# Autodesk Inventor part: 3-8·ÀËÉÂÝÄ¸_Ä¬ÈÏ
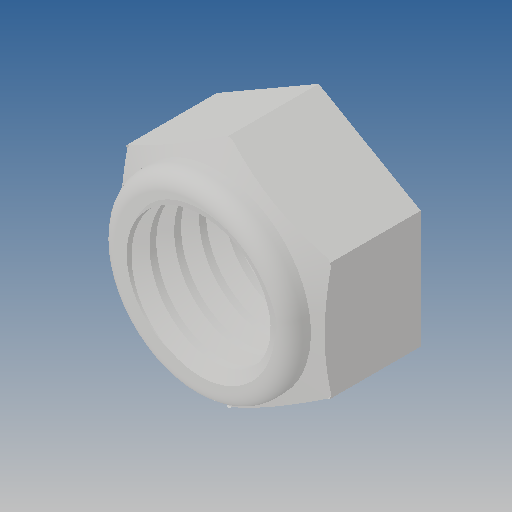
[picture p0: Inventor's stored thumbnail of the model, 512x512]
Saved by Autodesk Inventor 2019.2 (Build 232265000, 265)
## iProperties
Created: 2010-06
Part Number: 3-8·ÀËÉÂÝÄ¸_Ä¬ÈÏ
Material: Ogólny
Document SubType Name: Modeling
Designer: CADENGINEERING4
Density: 1 g/cm^3
Appearance: Domyślna
Author: CADENGINEERING4
Revision Number: ÈÎºÎ
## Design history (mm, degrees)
feature "NONE"
node "Bryła1"
